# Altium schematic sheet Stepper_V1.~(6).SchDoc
size A4; SheetNumber: 4; SheetTotal: 7
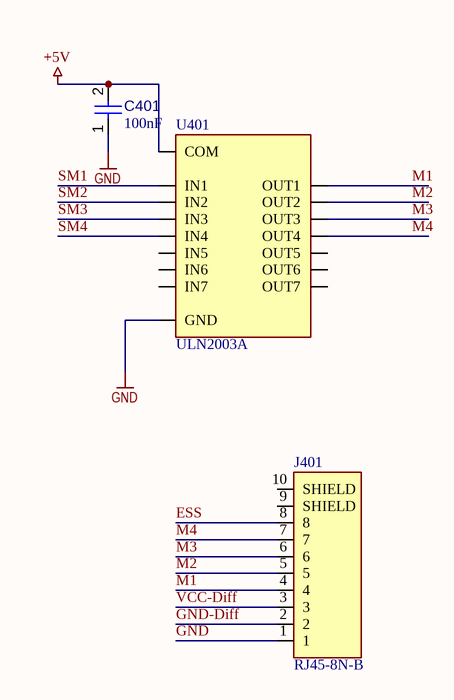
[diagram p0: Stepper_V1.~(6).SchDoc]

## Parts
C401  value 100nF  [CAPC1608X90X40NL10T20]  (hidden comment: Capacitor 100 nF +/-10% 50 V 0603)
J401  RJ45-8N-B  [TE_RJ45-8N-B]
U401  ULN2003A  [TSSOP-16-TI]

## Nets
+5V: C401.2 U401.9(COM)
GND: C401.1 J401.1 U401.8(GND)
ESS: J401.8
GND-Diff: J401.2
M1: J401.4 U401.16(OUT1)
M2: J401.5 U401.15(OUT2)
M3: J401.6 U401.14(OUT3)
M4: J401.7 U401.13(OUT4)
SM1: U401.1(IN1)
SM2: U401.2(IN2)
SM3: U401.3(IN3)
SM4: U401.4(IN4)
VCC-Diff: J401.3

Not connected (* = marked no-connect by the designer): J401 9(SHIELD) 10(SHIELD); U401 5(IN5) 6(IN6) 7(IN7) 10(OUT7) 11(OUT6) 12(OUT5)

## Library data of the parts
C401 = CMP-001-00017-6: Chip Capacitor, 100 nF, +/- 10%, 50 V, 0603 (1608 Metric); Voltage Rating: 50V; Capacitor Type: Ceramic
J401 = RJ45-8N-B: RJ Jack / Signal Line EMI/RFI Filters 6 TERM LOW PROFILE BLOCK INDUCTOR 8 PIN
U401 = ULN2003A: DARLINGTON ARRAY 7NPN, 2003, DIP16; Transistor Polarity:NPN; Collector Emitter Voltage V(br)ceo:50V; DC Collector Current:500mA; DC Current Gain hFE:1000; Operating Temperature Range:-20Â°C to +85Â°C; Transistor Case Style:DIP; No. of Pins:16; SVHC:No SVH; MF: STMicroelectronics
